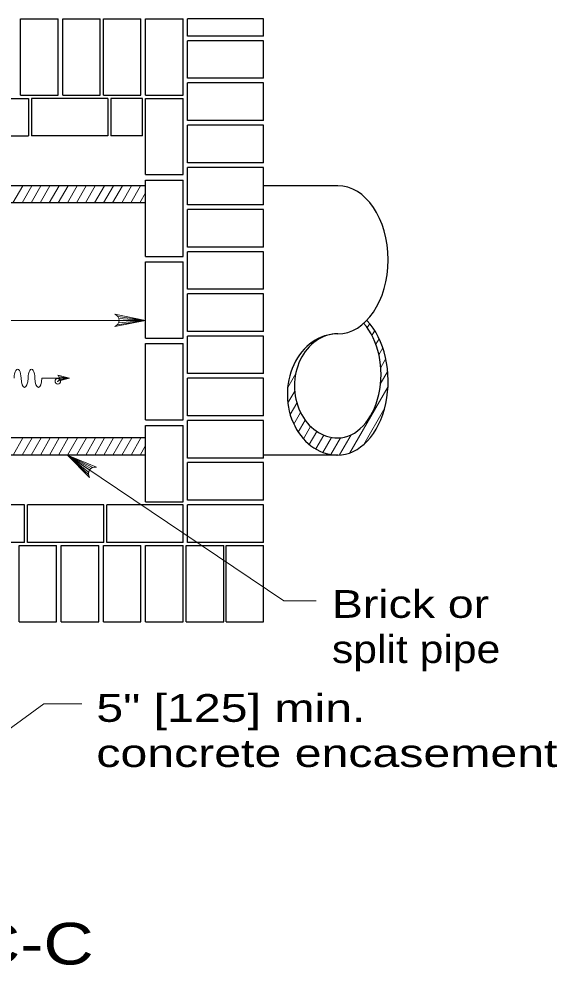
# Model space of a CAD drawing. Extents: x 750.7 to 784.7, y 860.1 to 882.1.
# Drawn here: x 770.77 to 773.87, y 867.66 to 873.11 of the extents above; entities that cross this region are included whole.
import ezdxf

# ---------------------------------------------------------------- set-up
doc = ezdxf.new("R2010")
doc.units = 0
doc.header["$LTSCALE"] = 0.064
doc.header["$PDMODE"] = 32
doc.header["$PDSIZE"] = 0.032
doc.layers.add('1', color=7, linetype='Continuous', lineweight=13)

msp = doc.modelspace()

# ---------------------------------------------------------------- linework, layer by layer
at = {"layer": '1', "lineweight": 25}
for p, q in [((770.779, 872.67283), (770.779, 873.11242)), ((770.779, 873.11242), (770.99525, 873.11242)), ((771.02208, 872.67283), (771.02208, 873.11242)), ((771.02208, 873.11242), (771.23833, 873.11242)), ((771.2565, 872.67283), (771.2565, 873.11242)), ((771.2565, 873.11242), (771.47275, 873.11242)), ((771.49958, 872.67283), (771.49958, 873.11242)), ((771.49958, 873.11242), (771.71583, 873.11242)), ((771.71583, 872.67283), (771.71583, 873.11242)), ((772.18, 873.11242), (771.74042, 873.11242)), ((771.74042, 873.01325), (771.74042, 873.11242)), ((772.18, 873.01325), (772.18, 873.11242)), ((772.18, 873.01325), (771.74042, 873.01325)), ((772.18, 872.9865), (771.74042, 872.9865)), ((771.74042, 872.77017), (771.74042, 872.9865)), ((772.18, 872.77017), (772.18, 872.9865)), ((772.18, 872.77017), (771.74042, 872.77017)), ((772.18, 872.74342), (771.74042, 872.74342)), ((771.74042, 872.52708), (771.74042, 872.74342)), ((772.18, 872.52708), (772.18, 872.74342)), ((770.3845, 872.65475), (770.82408, 872.65467)), ((770.82408, 872.65467), (770.82408, 872.43842)), ((771.28167, 872.65475), (770.84208, 872.65467)), ((770.84208, 872.65467), (770.84208, 872.43842)), ((771.28167, 872.65467), (771.28167, 872.43842)), ((771.29983, 872.65467), (771.29983, 872.43842)), ((771.48142, 872.65467), (771.29983, 872.65467)), ((771.48142, 872.43842), (771.48142, 872.65467)), ((771.49958, 872.67283), (771.71583, 872.67283)), ((771.49958, 872.21517), (771.49958, 872.65467)), ((771.49958, 872.65467), (771.71583, 872.65467)), ((771.71583, 872.21517), (771.71583, 872.65467)), ((772.18, 872.52708), (771.74042, 872.52708)), ((772.18, 872.50033), (771.74042, 872.50033)), ((771.74042, 872.284), (771.74042, 872.50033)), ((772.18, 872.284), (772.18, 872.50033)), ((770.3845, 872.43842), (770.82408, 872.43842)), ((771.28167, 872.43842), (770.84208, 872.43842)), ((771.48142, 872.43842), (771.29983, 872.43842)), ((772.18, 872.284), (771.74042, 872.284)), ((771.49958, 872.21517), (771.71583, 872.21517)), ((772.18, 872.25725), (771.74042, 872.25725)), ((771.74042, 872.04092), (771.74042, 872.25725)), ((772.18, 872.04092), (772.18, 872.25725)), ((771.49958, 871.744), (771.49958, 872.18358)), ((771.49958, 872.18358), (771.71583, 872.18358)), ((771.71583, 871.744), (771.71583, 872.18358)), ((771.49958, 872.15142), (770.29483, 872.15142)), ((772.608, 872.15142), (772.18, 872.15142)), ((771.49958, 872.05283), (770.23808, 872.05283)), ((772.18, 872.04092), (771.74042, 872.04092)), ((772.18, 872.01417), (771.74042, 872.01417)), ((771.74042, 871.79783), (771.74042, 872.01417)), ((772.18, 871.79783), (772.18, 872.01417)), ((772.18, 871.79783), (771.74042, 871.79783)), ((771.49958, 871.744), (771.71583, 871.744)), ((772.18, 871.77108), (771.74042, 871.77108)), ((771.74042, 871.55475), (771.74042, 871.77108)), ((772.18, 871.55475), (772.18, 871.77108)), ((771.49958, 871.27292), (771.49958, 871.7125)), ((771.49958, 871.7125), (771.71583, 871.7125)), ((771.71583, 871.27292), (771.71583, 871.7125)), ((772.18, 871.55475), (771.74042, 871.55475)), ((772.18, 871.528), (771.74042, 871.528)), ((771.74042, 871.31167), (771.74042, 871.528)), ((772.18, 871.31167), (772.18, 871.528)), ((772.18, 871.31167), (771.74042, 871.31167)), ((772.18, 871.28492), (771.74042, 871.28492)), ((771.74042, 871.06858), (771.74042, 871.28492)), ((772.18, 871.06858), (772.18, 871.28492)), ((771.49958, 871.27292), (771.71583, 871.27292)), ((771.49958, 870.80183), (771.49958, 871.24133)), ((771.49958, 871.24133), (771.71583, 871.24133)), ((771.71583, 870.80183), (771.71583, 871.24133)), ((772.18, 871.06858), (771.74042, 871.06858)), ((772.18, 871.04183), (771.74042, 871.04183)), ((771.74042, 870.8255), (771.74042, 871.04183)), ((772.18, 870.8255), (772.18, 871.04183)), ((771.49958, 870.80183), (771.71583, 870.80183)), ((772.18, 870.8255), (771.74042, 870.8255)), ((772.18, 870.79875), (771.74042, 870.79875)), ((771.74042, 870.58242), (771.74042, 870.79875)), ((772.18, 870.58242), (772.18, 870.79875)), ((771.49958, 870.77025), (771.71583, 870.77025)), ((771.49958, 870.33067), (771.49958, 870.77025)), ((771.71583, 870.33067), (771.71583, 870.77025)), ((771.49958, 870.69817), (770.23808, 870.69817)), ((771.49958, 870.59958), (770.29483, 870.59958)), ((772.18, 870.58242), (771.74042, 870.58242)), ((772.608, 870.59958), (772.18, 870.59958)), ((772.18, 870.55567), (771.74042, 870.55567)), ((771.74042, 870.33933), (771.74042, 870.55567)), ((772.18, 870.33933), (772.18, 870.55567)), ((770.80058, 870.31258), (770.36108, 870.31258)), ((770.80058, 870.09625), (770.80058, 870.31258)), ((771.25825, 870.31258), (770.81867, 870.31258)), ((771.25825, 870.09625), (771.25825, 870.31258)), ((771.71583, 870.31258), (771.27633, 870.31258)), ((771.27633, 870.09625), (771.27633, 870.31258)), ((771.49958, 870.33067), (771.71583, 870.33067)), ((771.71583, 870.09625), (771.71583, 870.31258)), ((772.18, 870.33933), (771.74042, 870.33933)), ((772.18, 870.31258), (771.74042, 870.31258)), ((771.74042, 870.09625), (771.74042, 870.31258)), ((772.18, 870.09625), (772.18, 870.31258)), ((770.80058, 870.09625), (770.36108, 870.09625)), ((771.71583, 870.09625), (771.27633, 870.09625)), ((772.18, 870.09625), (771.74042, 870.09625)), ((770.77033, 869.63858), (770.77033, 870.07817)), ((770.77033, 870.07817), (770.98658, 870.07817)), ((770.98658, 869.63858), (770.98658, 870.07817)), ((771.01342, 869.63858), (771.01342, 870.07817)), ((771.01342, 870.07817), (771.22967, 870.07817)), ((771.22967, 869.63858), (771.22967, 870.07817)), ((771.2565, 869.63858), (771.2565, 870.07817)), ((771.2565, 870.07817), (771.47275, 870.07817)), ((771.47275, 869.63858), (771.47275, 870.07817)), ((771.49958, 869.63858), (771.49958, 870.07808)), ((771.49958, 870.07808), (771.71583, 870.07808)), ((771.71583, 869.63858), (771.71583, 870.07808)), ((771.734, 869.63858), (771.734, 870.07817)), ((771.734, 870.07817), (771.95025, 870.07817)), ((771.95025, 869.63858), (771.95025, 870.07817)), ((771.96367, 869.63858), (771.96367, 870.07808)), ((771.96367, 870.07808), (772.18, 870.07808)), ((772.18, 869.63858), (772.18, 870.07808)), ((770.77033, 869.63858), (770.98658, 869.63858)), ((771.01342, 869.63858), (771.22967, 869.63858)), ((771.2565, 869.63858), (771.47275, 869.63858)), ((771.49958, 869.63858), (771.71583, 869.63858)), ((771.734, 869.63858), (771.95025, 869.63858)), ((771.96367, 869.63858), (772.18, 869.63858))]:
    msp.add_line(p, q, dxfattribs=at)
at = {"layer": '1'}
for p, q in [((770.73458, 872.05283), (770.79133, 872.15142)), ((770.78692, 872.05283), (770.84358, 872.15142)), ((770.83917, 872.05283), (770.89583, 872.15142)), ((770.8915, 872.05283), (770.94817, 872.15142)), ((770.94375, 872.05283), (771.00042, 872.15142)), ((770.99608, 872.05283), (771.05275, 872.15142)), ((771.04833, 872.05283), (771.105, 872.15142)), ((771.10067, 872.05283), (771.15733, 872.15142)), ((771.15292, 872.05283), (771.20958, 872.15142)), ((771.20517, 872.05283), (771.26192, 872.15142)), ((771.2575, 872.05283), (771.31417, 872.15142)), ((771.30975, 872.05283), (771.36642, 872.15142)), ((771.36208, 872.05283), (771.41875, 872.15142)), ((771.41433, 872.05283), (771.471, 872.15142)), ((771.46667, 872.05283), (771.49958, 872.11008)), ((771.33925, 871.39792), (771.49958, 871.3755)), ((769.42667, 871.3755), (771.49958, 871.3755)), ((771.33733, 871.35067), (771.49958, 871.3755)), ((771.3435, 871.36108), (771.49958, 871.3755)), ((771.34467, 871.38683), (771.49958, 871.3755)), ((771.34633, 871.3755), (771.49958, 871.3755)), ((772.77825, 871.33283), (772.792, 871.35675)), ((772.80542, 871.28917), (772.82117, 871.31658)), ((772.46633, 871.245), (772.47425, 871.25875)), ((772.82817, 871.23767), (772.84667, 871.27)), ((772.84567, 871.17725), (772.86825, 871.21658)), ((772.85625, 871.10467), (772.88525, 871.15508)), ((772.31908, 870.98892), (772.36542, 871.0695)), ((772.85508, 871.01175), (772.89617, 871.08317)), ((770.9015, 871.042), (771.06158, 871.042)), ((771.06017, 871.042), (771.00208, 871.042)), ((772.32008, 870.89958), (772.3595, 870.96817)), ((772.67758, 870.612), (772.898, 870.99542)), ((772.33375, 870.8325), (772.37217, 870.89925)), ((772.75783, 870.66058), (772.87883, 870.87117)), ((772.3545, 870.77758), (772.39325, 870.845)), ((772.38033, 870.7315), (772.42, 870.80058)), ((772.41025, 870.69267), (772.4515, 870.76433)), ((770.73583, 870.59958), (770.7925, 870.69817)), ((770.78808, 870.59958), (770.84483, 870.69817)), ((770.84042, 870.59958), (770.89708, 870.69817)), ((770.89267, 870.59958), (770.94933, 870.69817)), ((770.945, 870.59958), (771.00167, 870.69817)), ((770.99725, 870.59958), (771.05392, 870.69817)), ((771.04958, 870.59958), (771.10625, 870.69817)), ((771.10183, 870.59958), (771.1585, 870.69817)), ((771.15417, 870.59958), (771.21083, 870.69817)), ((771.20642, 870.59958), (771.26308, 870.69817)), ((771.25867, 870.59958), (771.31542, 870.69817)), ((771.311, 870.59958), (771.36767, 870.69817)), ((771.36325, 870.59958), (771.41992, 870.69817)), ((771.41558, 870.59958), (771.47225, 870.69817)), ((772.444, 870.66042), (772.48717, 870.73558)), ((772.48133, 870.63442), (772.52725, 870.71425)), ((772.5225, 870.615), (772.57208, 870.70125)), ((772.56783, 870.60292), (772.62292, 870.69883)), ((772.61833, 870.59983), (772.68517, 870.71608)), ((771.46783, 870.59958), (771.49958, 870.65475)), ((771.17642, 870.51358), (771.04958, 870.59958)), ((771.17067, 870.5), (771.04958, 870.59958)), ((771.16992, 870.488), (771.04958, 870.59958)), ((771.18417, 870.52208), (771.04958, 870.59958)), ((771.19483, 870.52817), (771.04958, 870.59958))]:
    msp.add_line(p, q, dxfattribs=at)
at = {"layer": '1', "lineweight": 25}
for points in [[(770.779, 872.67283), (770.99525, 872.67283), (770.99525, 873.11242)], [(771.02208, 872.67283), (771.23833, 872.67283), (771.23833, 873.11242)], [(771.2565, 872.67283), (771.47275, 872.67283), (771.47275, 873.11242)], [(771.25825, 870.09625), (770.81867, 870.09625), (770.81867, 870.31258)]]:
    msp.add_lwpolyline(points, dxfattribs=at)
at = {"layer": '1'}
for points in [[(771.3225, 871.34008), (771.49958, 871.3755), (771.3225, 871.41092)], [(770.99342, 871.059), (771.06158, 871.042), (770.99333, 871.025)], [(771.00067, 871.0505), (771.06158, 871.042), (771.00092, 871.0335)], [(771.17625, 870.47083), (771.04958, 870.59958), (771.21608, 870.5295)], [(771.04958, 870.59958), (772.29633, 869.75917), (772.48425, 869.75917)], [(770.60342, 868.94133), (770.91325, 869.16508), (771.13117, 869.16508)]]:
    msp.add_lwpolyline(points, dxfattribs=at)
for centre, start, end in [((771.30819, 871.37552), 292.08605, 67.91218), ((771.20803, 870.49219), 77.95483, 213.78096)]:
    msp.add_arc(centre, 0.03822, start, end, dxfattribs=at)
at = {"layer": '1', "lineweight": 25}
for centre, major_axis, ratio, start_param, end_param in [((772.60797, 871.72465), (0, 0.42676), 0.681413, 3.1415927, 6.2831853), ((772.60797, 871.02633), (0, 0.42676), 0.681413, 3.1346347, 5.6706328), ((772.60797, 871.06467), (0, 0.3665), 0.681413, 3.1415896, 5.6423266), ((772.60797, 870.94873), (0, 0.34916), 0.832832, 6.2831853, 9.4602862), ((772.60797, 870.99803), (0, 0.29987), 0.832832, 6.2831853, 9.424778)]:
    msp.add_ellipse(centre, major_axis=major_axis, ratio=ratio, start_param=start_param, end_param=end_param, dxfattribs=at)
at = {"layer": '1'}
for centre, major_axis, ratio, start_param, end_param in [((770.76152, 871.04199), (0, -0.05257), 0.380456, 1.5707963, 4.712389), ((770.84153, 871.04199), (0, -0.05257), 0.380456, 1.5707963, 4.712389), ((770.80153, 871.04199), (0, -0.05257), 0.380456, 4.712389, 7.8539816), ((770.88154, 871.04199), (0, -0.05257), 0.380456, 4.712389, 7.8539816), ((770.99344, 871.04199), (0, 0.017), 0.5, 3.3984695, 6.0297764)]:
    msp.add_ellipse(centre, major_axis=major_axis, ratio=ratio, start_param=start_param, end_param=end_param, dxfattribs=at)
msp.add_point((770.99342, 871.02483), dxfattribs=at)

# ---------------------------------------------------------------- texts
for s, height, width, p in [('Brick or', 0.16, 1.25, (772.57425, 869.66133)), ('split pipe', 0.16, 1.15, (772.57425, 869.40133)), ('5" [125] min.', 0.16, 1.3, (771.21567, 869.06225)), ('concrete encasement', 0.16, 1.3, (771.21567, 868.80225)), ('SECTION C-C', 0.24, 1.25, (768.59242, 867.66417))]:
    msp.add_text(s, height=height, dxfattribs=dict(at, width=width)).set_placement(p)

doc.saveas('drawing.dxf')
